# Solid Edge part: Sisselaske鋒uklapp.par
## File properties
Author: Türk
Template: Iso Part.par
Last saved by: Türk
Revision: 3
Application: Solid Edge
Accuracy: 0,990
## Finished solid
Body 1: solid body, 13 faces, 26 edges, 16 vertices.
  Faces by surface: plane 6, cone 4, cylinder 3
  Edges by curve: intersection 12, circle 10, line 4
Bounding box of the edges (mm): 94.000 x 10.000 x 145.000, from (-47, -5, -67.5) to (47, 5, 77.5).
Cylindrical faces by radius (mm): R5 x1, R47 x2
Conical faces (half-angle, radius in mm at the cone's reference point): 45 deg R46.5 x2, 45 deg R47 x2
Planar faces by outward normal: +y 2, +z 1, -y 2, -z 1
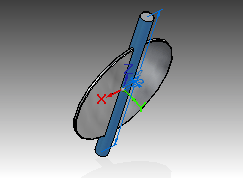
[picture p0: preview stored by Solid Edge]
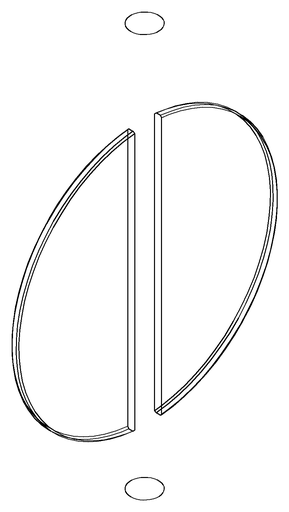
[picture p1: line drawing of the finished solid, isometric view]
